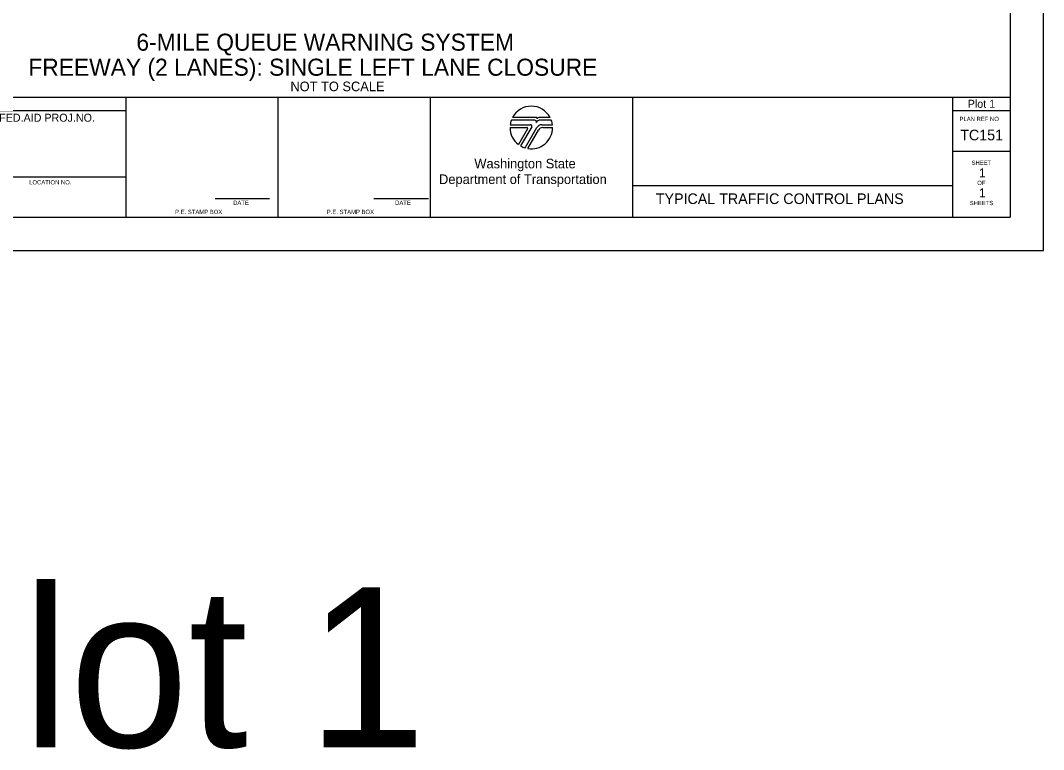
# Model space of a CAD drawing. Extents: x 99999.1 to 100035.7, y 99995 to 100010.7.
# Drawn here: x 100006.46 to 100016.06, y 99995.01 to 100001.84 of the extents above; entities that cross this region are included whole.
import ezdxf

# ---------------------------------------------------------------- set-up
doc = ezdxf.new("R2010")
doc.units = 0
for name, color, linetype in [('SH_DE_DetailHeading1Text', 7, 'Continuous'), ('SH_DE_DetailHeading3Text', 7, 'Continuous'), ('SH_GI_PlotLimits', 7, 'Continuous'), ('SH_GI_SheetBorder', 7, 'Continuous'), ('SH_GI_SheetLocationText', 7, 'Continuous'), ('SH_GI_SheetTextInCells', 7, 'Continuous'), ('SH_GI_TitleBlockText', 7, 'Continuous'), ('SH_GI_WSDOTLogo', 7, 'Continuous')]:
    doc.layers.add(name, color=color, linetype=linetype)

msp = doc.modelspace()

# ---------------------------------------------------------------- linework, layer by layer
at = {"layer": 'SH_GI_PlotLimits'}
msp.add_lwpolyline([(99999.0625, 99999.6875), (100016.0625, 99999.6875), (100016.0625, 100010.6875), (99999.0625, 100010.6875)], close=True, dxfattribs=at)
at = {"layer": 'SH_GI_SheetBorder'}
for p, q in [((100015.75, 100010.375), (100015.75, 100000)), ((100000, 100001.1259), (100015.75, 100001.1259)), ((100007.4566, 100000), (100007.4566, 100001.1259)), ((100008.8828, 100000), (100008.8828, 100001.1259)), ((100010.3089, 100001.1259), (100010.3089, 100000)), ((100012.2055, 100001.1259), (100012.2055, 100000)), ((100015.2079, 100001.1259), (100015.2079, 100000)), ((100000, 100001.0008), (100007.4566, 100001.0008)), ((100015.2079, 100001.0008), (100015.75, 100001.0008)), ((100015.2079, 100000.6176), (100015.75, 100000.6176)), ((100007.4566, 100000.3753), (100005.4466, 100000.3753)), ((100012.2055, 100000.2955), (100015.2079, 100000.2955)), ((100008.2903, 100000.1733), (100008.802, 100000.1733)), ((100009.7797, 100000.1733), (100010.2914, 100000.1733)), ((100000, 100000), (100015.75, 100000))]:
    msp.add_line(p, q, dxfattribs=at)
at = {"layer": 'SH_GI_WSDOTLogo'}
for p, q in [((100011.059, 100000.8661), (100011.2496, 100000.8661)), ((100011.2894, 100000.9094), (100011.0697, 100000.9094)), ((100011.303, 100000.9354), (100011.0815, 100000.9354)), ((100011.433, 100000.9354), (100011.3351, 100000.9354)), ((100011.343, 100000.9094), (100011.3429, 100000.9094)), ((100011.4448, 100000.9094), (100011.343, 100000.9094)), ((100011.3558, 100000.8661), (100011.4555, 100000.8661)), ((100011.0572, 100000.84), (100011.2148, 100000.84)), ((100011.222, 100000.8277), (100011.1364, 100000.6807)), ((100011.261, 100000.8464), (100011.1567, 100000.6672)), ((100011.1989, 100000.6487), (100011.3089, 100000.839)), ((100011.2244, 100000.6428), (100011.3242, 100000.8156)), ((100011.3655, 100000.8394), (100011.4572, 100000.8394))]:
    msp.add_line(p, q, dxfattribs=at)
for centre, radius, start, end in [((100011.2572, 100000.84), 0.2, 28.47865, 151.53204), ((100011.2572, 100000.84), 0.2, 159.69598, 172.50569), ((100011.2497, 100000.853), 0.0131, 329.76834, 90), ((100011.2894, 100000.8946), 0.0148, 327.8418, 89.99855), ((100011.3429, 100000.861), 0.0484, 89.99529, 147.82376), ((100011.303, 100000.9263), 0.00903, 329.87418, 90.00328), ((100011.3558, 100000.8119), 0.0542, 90, 149.99738), ((100011.3352, 100000.9066), 0.0287, 90.00721, 148.16763), ((100011.2572, 100000.84), 0.2, 7.49431, 20.29406), ((100011.2572, 100000.84), 0.2, 179.99864, 232.84327), ((100011.2149, 100000.8318), 0.0082, 329.74356, 90), ((100011.2572, 100000.84), 0.2, 260.54554, 359.80857), ((100011.3654, 100000.7918), 0.0476, 90, 150.05432), ((100011.2572, 100000.84), 0.2, 239.79292, 253.0448)]:
    msp.add_arc(centre, radius, start, end, dxfattribs=at)

# ---------------------------------------------------------------- texts
at = {"layer": 'SH_DE_DetailHeading1Text'}
for s, p in [('6-MILE QUEUE WARNING SYSTEM', (100007.5522, 100001.5606)), ('FREEWAY (2 LANES): SINGLE LEFT LANE CLOSURE', (100006.5383, 100001.3259))]:
    msp.add_text(s, height=0.16, rotation=360, dxfattribs=at).set_placement(p)
at = {"layer": 'SH_DE_DetailHeading3Text'}
msp.add_text('NOT TO SCALE', height=0.09, dxfattribs=at).set_placement((100008.9969, 100001.1809))
at = {"layer": 'SH_GI_SheetBorder'}
msp.add_text('PLAN REF NO', height=0.040032, dxfattribs=at).set_placement((100015.2747, 100000.9008))
at = {"layer": 'SH_GI_SheetLocationText'}
for height, p in [(0.075, (100015.3518, 100001.025)), (1.5, (100005.1422, 99995.0267))]:
    msp.add_text('Plot 1', height=height, dxfattribs=at).set_placement(p)
at = {"layer": 'SH_GI_SheetTextInCells'}
for s, height, p in [('FED.AID PROJ.NO.', 0.07506, (100006.2652, 100000.8945)), ('Washington State', 0.090072, (100010.7229, 100000.4571)), ('SHEET', 0.04003, (100015.3877, 100000.4896)), ('Department of Transportation', 0.090072, (100010.3916, 100000.3101)), ('LOCATION NO.', 0.040032, (100006.5465, 100000.3067)), ('OF', 0.04003, (100015.4406, 100000.3008)), ('DATE', 0.04003, (100008.4597, 100000.1141)), ('DATE', 0.04003, (100009.9794, 100000.1141)), ('SHEETS', 0.04003, (100015.3698, 100000.112)), ('P.E. STAMP BOX', 0.040032, (100007.915, 100000.0286)), ('P.E. STAMP BOX', 0.040032, (100009.339, 100000.0286))]:
    msp.add_text(s, height=height, dxfattribs=at).set_placement(p)
at = {"layer": 'SH_GI_TitleBlockText'}
for s, height, p in [('TC151', 0.1, (100015.2811, 100000.72)), ('1', 0.085, (100015.4566, 100000.3723)), ('TYPICAL TRAFFIC CONTROL PLANS', 0.1, (100012.4251, 100000.1224)), ('1', 0.085, (100015.4566, 100000.1843))]:
    msp.add_text(s, height=height, dxfattribs=at).set_placement(p)

doc.saveas('drawing.dxf')
